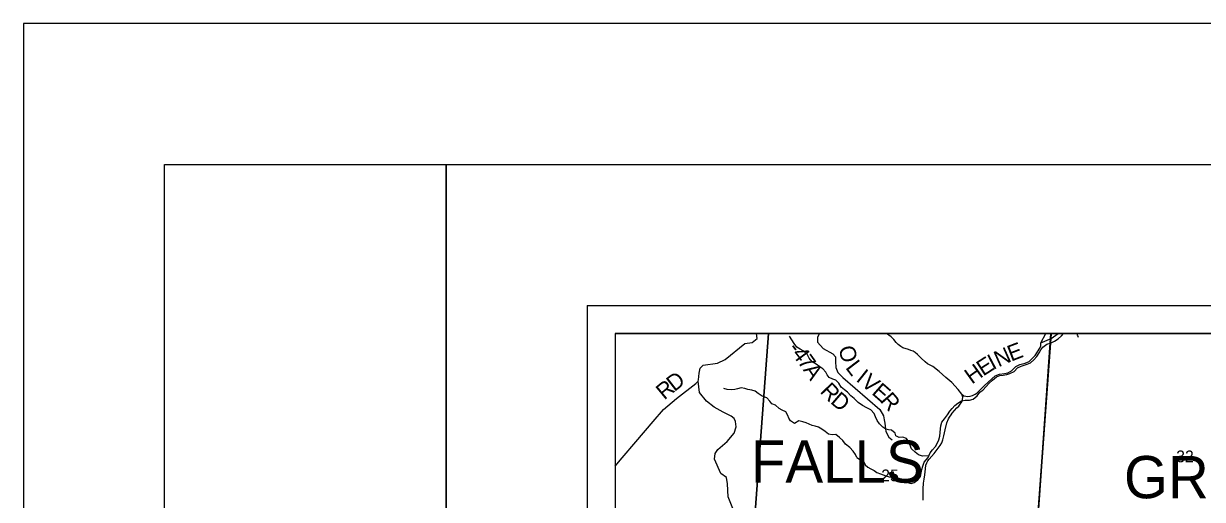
# Model space of a CAD drawing. Extents: x 0 to 34, y 0 to 22.
# Drawn here: x 0 to 4.184, y 20.311 to 22 of the extents above; entities that cross this region are included whole.
import ezdxf

# ---------------------------------------------------------------- set-up
doc = ezdxf.new("R2010")
doc.units = 0
for name, color, linetype in [('GM_X_Corporation', 7, 'Continuous'), ('GM_X_County_Road', 7, 'Continuous'), ('GM_X_Minor_River', 7, 'Continuous'), ('GM_X_Section_Text', 7, 'Continuous'), ('GM_X_Township_Road', 7, 'Continuous'), ('GM_X_Township_Road_Text', 7, 'Continuous'), ('GM_X_Township_Text', 7, 'Continuous'), ('SH_Border', 7, 'Continuous'), ('SH_Cut_Line', 7, 'Continuous'), ('SH_Data', 7, 'Continuous')]:
    doc.layers.add(name, color=color, linetype=linetype)

msp = doc.modelspace()

# ---------------------------------------------------------------- linework, layer by layer
at = {"layer": 'GM_X_Corporation'}
for points in [[(2.6442, 20.9), (2.1, 20.9), (2.1, 20.0905), (2.5811, 20.0615)], [(3.646, 20.9), (2.6442, 20.9), (2.5811, 20.0615), (3.5832, 20.0065)], [(8.9, 18.631), (8.9, 20.9), (3.6477, 20.9), (3.6464, 20.8827), (3.5665, 19.797), (3.566, 19.7906), (3.507, 18.9883), (4.2931, 18.935), (4.421, 18.9263), (4.4362, 18.9253), (5.6003, 18.8464), (6.4706, 18.7873), (6.895, 18.7585), (7.0255, 18.7497), (7.0714, 18.7466), (7.0845, 18.7457), (7.389, 18.725), (7.8088, 18.6965), (7.8353, 18.6952)], [(4.6577, 20.9), (3.646, 20.9), (3.5832, 20.0065), (4.594, 19.9182)]]:
    msp.add_lwpolyline(points, close=True, dxfattribs=at)
at = {"layer": 'GM_X_County_Road'}
for points in [[(3.33, 20.6852), (3.3172, 20.7011), (3.2942, 20.7257), (3.2736, 20.7438), (3.2491, 20.7651), (3.2268, 20.7825), (3.2182, 20.7873), (3.2086, 20.793), (3.1997, 20.7998), (3.1856, 20.8127), (3.1725, 20.8253), (3.164, 20.8326), (3.1568, 20.8369), (3.1493, 20.84), (3.1409, 20.8431), (3.1211, 20.8497), (3.1134, 20.8535), (3.1045, 20.8607), (3.097, 20.8685), (3.0883, 20.8793), (3.0789, 20.8882), (3.0631, 20.9)], [(3.1929, 20.3091), (3.1934, 20.3485), (3.1945, 20.3684), (3.1964, 20.383), (3.199, 20.3991), (3.2013, 20.4198), (3.2027, 20.4334), (3.2053, 20.4411), (3.2089, 20.4481), (3.2144, 20.4547), (3.2316, 20.4746), (3.2531, 20.5025), (3.2592, 20.5121), (3.2627, 20.5225), (3.2665, 20.5375), (3.271, 20.5588), (3.2773, 20.5836), (3.2824, 20.5967), (3.2857, 20.6033), (3.2917, 20.6117), (3.2958, 20.6178), (3.3122, 20.6368), (3.3189, 20.6425), (3.3245, 20.649), (3.3278, 20.6538), (3.3312, 20.6594), (3.3326, 20.6664), (3.3331, 20.6736), (3.3326, 20.6777), (3.33, 20.6852)]]:
    msp.add_lwpolyline(points, dxfattribs=at)
at = {"layer": 'GM_X_Minor_River'}
for p, q in [((2.7267, 20.8782), (2.7183, 20.8903)), ((2.7354, 20.8645), (2.7267, 20.8782)), ((2.7441, 20.852), (2.7354, 20.8645)), ((2.7558, 20.8441), (2.7441, 20.852)), ((2.7694, 20.8376), (2.7558, 20.8441)), ((2.7812, 20.8267), (2.7694, 20.8376)), ((2.7883, 20.813), (2.7812, 20.8267)), ((2.7993, 20.7997), (2.7883, 20.813)), ((2.8133, 20.7914), (2.7993, 20.7997)), ((2.8266, 20.7816), (2.8133, 20.7914)), ((2.8364, 20.7751), (2.8266, 20.7816)), ((2.8478, 20.763), (2.8364, 20.7751)), ((2.8519, 20.7535), (2.8478, 20.763)), ((2.8591, 20.744), (2.8519, 20.7535)), ((2.8724, 20.738), (2.8591, 20.744)), ((2.883, 20.7342), (2.8724, 20.738)), ((2.894, 20.724), (2.883, 20.7342)), ((2.9019, 20.7099), (2.894, 20.724)), ((2.4976, 20.7012), (2.4858, 20.705)), ((2.5112, 20.7), (2.4976, 20.7012)), ((2.5241, 20.7019), (2.5112, 20.7)), ((2.5339, 20.7042), (2.5241, 20.7019)), ((2.5472, 20.7072), (2.5339, 20.7042)), ((2.56, 20.7046), (2.5472, 20.7072)), ((2.5703, 20.7016), (2.56, 20.7046)), ((2.585, 20.6985), (2.5703, 20.7016)), ((2.5964, 20.6955), (2.585, 20.6985)), ((2.607, 20.6868), (2.5964, 20.6955)), ((2.621, 20.6777), (2.607, 20.6868)), ((2.638, 20.672), (2.621, 20.6777)), ((2.649, 20.6599), (2.638, 20.672)), ((2.914, 20.6997), (2.9019, 20.7099)), ((2.9242, 20.6914), (2.914, 20.6997)), ((2.9356, 20.6785), (2.9242, 20.6914)), ((2.9481, 20.6694), (2.9356, 20.6785)), ((2.9625, 20.655), (2.9481, 20.6694)), ((2.6554, 20.6504), (2.649, 20.6599)), ((2.6683, 20.6455), (2.6554, 20.6504)), ((2.6812, 20.6337), (2.6683, 20.6455)), ((2.6918, 20.6284), (2.6812, 20.6337)), ((2.7058, 20.6216), (2.6918, 20.6284)), ((2.9776, 20.6444), (2.9625, 20.655)), ((2.9924, 20.6368), (2.9776, 20.6444)), ((3.0075, 20.6292), (2.9924, 20.6368)), ((3.0189, 20.6167), (3.0075, 20.6292)), ((2.7122, 20.6087), (2.7058, 20.6216)), ((2.7156, 20.5992), (2.7122, 20.6087)), ((2.7217, 20.5898), (2.7156, 20.5992)), ((2.7364, 20.5811), (2.7217, 20.5898)), ((2.7519, 20.5905), (2.7364, 20.5811)), ((2.7652, 20.5864), (2.7519, 20.5905)), ((2.7777, 20.5833), (2.7652, 20.5864)), ((3.0242, 20.6042), (3.0189, 20.6167)), ((3.0291, 20.591), (3.0242, 20.6042)), ((3.0378, 20.58), (3.0291, 20.591)), ((2.7887, 20.578), (2.7777, 20.5833)), ((2.7993, 20.5739), (2.7887, 20.578)), ((2.8095, 20.5712), (2.7993, 20.5739)), ((2.8208, 20.5678), (2.8095, 20.5712)), ((2.8333, 20.561), (2.8208, 20.5678)), ((2.8447, 20.5526), (2.8333, 20.561)), ((2.8568, 20.5428), (2.8447, 20.5526)), ((3.0495, 20.5678), (3.0378, 20.58)), ((3.0605, 20.5603), (3.0495, 20.5678)), ((3.0703, 20.5587), (3.0605, 20.5603)), ((3.0809, 20.5572), (3.0703, 20.5587)), ((3.0938, 20.5462), (3.0809, 20.5572)), ((3.0957, 20.5368), (3.0938, 20.5462)), ((2.8697, 20.5405), (2.8568, 20.5428)), ((2.8833, 20.5413), (2.8697, 20.5405)), ((2.8954, 20.5307), (2.8833, 20.5413)), ((2.9079, 20.5204), (2.8954, 20.5307)), ((2.9174, 20.5079), (2.9079, 20.5204)), ((2.9321, 20.4954), (2.9174, 20.5079)), ((3.1082, 20.5315), (3.0957, 20.5368)), ((3.1203, 20.5318), (3.1082, 20.5315)), ((3.1332, 20.5277), (3.1203, 20.5318)), ((3.1419, 20.5152), (3.1332, 20.5277)), ((3.1453, 20.5057), (3.1419, 20.5152)), ((3.151, 20.4913), (3.1453, 20.5057)), ((2.9442, 20.4829), (2.9321, 20.4954)), ((2.9522, 20.4712), (2.9442, 20.4829)), ((2.9575, 20.4595), (2.9522, 20.4712)), ((3.1642, 20.4784), (3.151, 20.4913)), ((3.1763, 20.4697), (3.1642, 20.4784)), ((3.1899, 20.4648), (3.1763, 20.4697)), ((3.2129, 20.4657), (3.1899, 20.4648)), ((3.1968, 20.4431), (3.2104, 20.4597)), ((2.9575, 20.4595), (2.9818, 20.4452)), ((2.9818, 20.4452), (2.9867, 20.4335)), ((2.9867, 20.4335), (2.9962, 20.4263)), ((2.9962, 20.4263), (3.0065, 20.4203)), ((3.0065, 20.4203), (3.0186, 20.4143)), ((3.1878, 20.4173), (3.1911, 20.4298)), ((3.1911, 20.4298), (3.1968, 20.4431)), ((3.0186, 20.4143), (3.0285, 20.4071)), ((3.0285, 20.4071), (3.041, 20.4015)), ((3.041, 20.4015), (3.0504, 20.3981)), ((3.0504, 20.3981), (3.0603, 20.3947)), ((3.0603, 20.3947), (3.072, 20.3918)), ((3.072, 20.3918), (3.0826, 20.3907)), ((3.0826, 20.3907), (3.0925, 20.3884)), ((3.0925, 20.3884), (3.1099, 20.3798)), ((3.1099, 20.3798), (3.1236, 20.3746)), ((3.1603, 20.3717), (3.1735, 20.3809)), ((3.1735, 20.3809), (3.1833, 20.3926)), ((3.1833, 20.3926), (3.1855, 20.4055)), ((3.1855, 20.4055), (3.1878, 20.4173)), ((3.1236, 20.3746), (3.1372, 20.3708)), ((3.1372, 20.3708), (3.1501, 20.3682)), ((3.1501, 20.3682), (3.1603, 20.3717))]:
    msp.add_line(p, q, dxfattribs=at)
msp.add_lwpolyline([(3.2104, 20.4597), (3.2172, 20.4761), (3.2259, 20.4871), (3.2361, 20.4996), (3.2437, 20.5125), (3.2483, 20.5224), (3.252, 20.5353), (3.2536, 20.5482), (3.2543, 20.5622), (3.2555, 20.572), (3.2589, 20.5849), (3.2683, 20.597), (3.2789, 20.6118), (3.2873, 20.6243), (3.2956, 20.6338), (3.3051, 20.6444), (3.3157, 20.6531), (3.3293, 20.6611), (3.3422, 20.6634), (3.3569, 20.6638), (3.3706, 20.6672), (3.3842, 20.6789), (3.3944, 20.6914), (3.4043, 20.699), (3.416, 20.7115), (3.427, 20.7244), (3.4384, 20.735), (3.4528, 20.7468), (3.4652, 20.7513), (3.4762, 20.7528), (3.4895, 20.7544), (3.5008, 20.7578), (3.5156, 20.7654), (3.5273, 20.7779), (3.5402, 20.7839), (3.5516, 20.7877), (3.5614, 20.7908), (3.5743, 20.7961), (3.5856, 20.8063), (3.5963, 20.8188), (3.6042, 20.8313), (3.6103, 20.8416), (3.6178, 20.8514), (3.6322, 20.862), (3.6474, 20.8673), (3.6591, 20.8734), (3.6724, 20.881), (3.6837, 20.892), (3.6906, 20.9)], dxfattribs=at)
at = {"layer": 'GM_X_Township_Road'}
for points in [[(2.1, 20.4292), (2.124, 20.4587), (2.1735, 20.5162), (2.2351, 20.5882), (2.2716, 20.6303), (2.3168, 20.6697), (2.386, 20.7231), (2.3947, 20.7307), (2.3951, 20.736), (2.3974, 20.7592), (2.4009, 20.777), (2.4119, 20.788), (2.4627, 20.7951), (2.4897, 20.8084), (2.56, 20.8644), (2.5862, 20.8682), (2.6037, 20.8818), (2.6011, 20.9)], [(2.8242, 20.9), (2.8237, 20.8994), (2.8176, 20.8854), (2.8183, 20.8699), (2.8384, 20.8467), (2.8725, 20.8284), (2.8812, 20.8171), (2.8816, 20.811), (2.8815, 20.8007), (2.8826, 20.7799), (2.8898, 20.7617), (2.9072, 20.7434), (3.039, 20.6302), (3.0522, 20.6082), (3.0545, 20.5939)], [(3.33, 20.6852), (3.3375, 20.6791), (3.3448, 20.6774), (3.3516, 20.6767), (3.3598, 20.6779), (3.3676, 20.6797), (3.3769, 20.6844), (3.384, 20.6894), (3.4101, 20.7156), (3.4478, 20.7501), (3.4633, 20.7557), (3.4812, 20.7576), (3.4937, 20.7603), (3.5062, 20.7678), (3.5218, 20.7834), (3.5355, 20.7898), (3.5552, 20.7951), (3.5685, 20.8004), (3.5898, 20.8216), (3.6069, 20.8485), (3.61, 20.8569), (3.6107, 20.8673), (3.6284, 20.9)], [(3.6107, 20.8673), (3.6466, 20.8822), (3.6714, 20.9)], [(3.7385, 20.897), (3.7409, 20.8927), (3.7428, 20.8876)], [(2.5175, 20.2787), (2.5005, 20.3201), (2.4989, 20.366), (2.4943, 20.3887), (2.475, 20.4031), (2.4521, 20.4537), (2.454, 20.4742), (2.4644, 20.489), (2.497, 20.517), (2.5225, 20.5462), (2.5297, 20.5683), (2.5272, 20.5875), (2.5221, 20.599), (2.5113, 20.6073), (2.4832, 20.6213), (2.4506, 20.6388), (2.4233, 20.6604), (2.3992, 20.6909), (2.3947, 20.7307)], [(3.0545, 20.5939), (3.0563, 20.5824), (3.0577, 20.5712), (3.06, 20.5528), (3.071, 20.5323), (3.0831, 20.5227)]]:
    msp.add_lwpolyline(points, dxfattribs=at)
at = {"layer": 'GM_X_Township_Text'}
msp.add_lwpolyline([(2.1, 19.0816), (2.4649, 19.0567), (2.4972, 19.0545), (2.509, 19.0572), (2.9513, 19.0267), (3.507, 18.9883), (3.566, 19.7906), (3.5665, 19.797), (3.6464, 20.8827), (3.6477, 20.9)], dxfattribs=at)
at = {"layer": 'SH_Border'}
for points in [[(0.5, 21.5), (1.5, 21.5), (1.5, 0.5), (0.5, 0.5)], [(1.5, 21.5), (33.5, 21.5), (33.5, 0.5), (1.5, 0.5)]]:
    msp.add_lwpolyline(points, close=True, dxfattribs=at)
at = {"layer": 'SH_Cut_Line'}
msp.add_lwpolyline([(0, 0), (34, 0), (34, 22), (0, 22)], close=True, dxfattribs=at)
at = {"layer": 'SH_Data'}
for p, q in [((2, 21), (9, 21)), ((2, 21), (2, 14)), ((2.1, 20.9), (2.1, 14.1)), ((2.1, 20.9), (8.9, 20.9))]:
    msp.add_line(p, q, dxfattribs=at)

# ---------------------------------------------------------------- texts
at = {"layer": 'GM_X_Section_Text'}
for s, p in [('32', (4.0909, 20.443)), ('25', (3.0438, 20.3755))]:
    msp.add_text(s, height=0.04186, rotation=0, dxfattribs=at).set_placement(p)
at = {"layer": 'GM_X_Township_Road_Text'}
for s, rotation, p in [('-', 307.7114, (2.7106, 20.8457)), ('4', 306.3381, (2.7246, 20.8275)), ('O', 284.349, (2.8918, 20.8492)), ('N', 24.2414, (3.4602, 20.7799)), ('E', 20.9824, (3.505, 20.8001)), ('7', 305.044, (2.7452, 20.7996)), ('L', 307.3732, (2.915, 20.7785)), ('E', 32.814, (3.4058, 20.7471)), ('I', 27.7869, (3.4403, 20.7695)), ('D', 37.9191, (2.3097, 20.6918)), ('A', 304.0558, (2.7651, 20.7712)), ('I', 321.5904, (2.9516, 20.7338)), ('V', 319.2774, (2.9694, 20.7197)), ('H', 35.7435, (3.3658, 20.7183)), ('R', 39.6826, (2.2741, 20.6623)), ('R', 313.9788, (2.8242, 20.6925)), ('E', 318.7907, (3.0072, 20.6871)), ('D', 319.3579, (2.8608, 20.655)), ('R', 311.1389, (3.0377, 20.6606))]:
    msp.add_text(s, height=0.0568, rotation=rotation, dxfattribs=at).set_placement(p)
at = {"layer": 'GM_X_Township_Text'}
for s, p in [('FALLS', (2.5814, 20.3709)), ('GREEN', (3.9056, 20.3154))]:
    msp.add_text(s, height=0.15, rotation=0, dxfattribs=at).set_placement(p)

doc.saveas('drawing.dxf')
